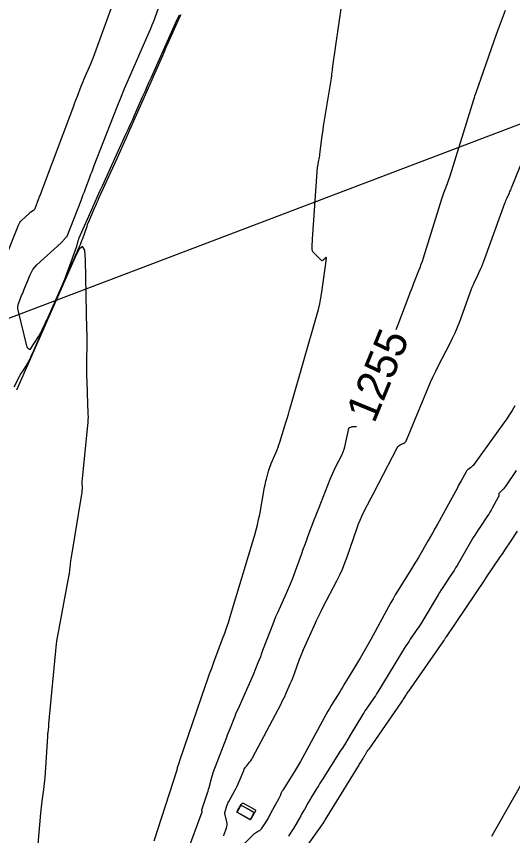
# Model space of a CAD drawing. Extents: x 658976 to 668726, y 639543 to 647196.
# Drawn here: x 661779.9 to 661874.7, y 641576.8 to 641733.2 of the extents above; entities that cross this region are included whole.
import ezdxf

# ---------------------------------------------------------------- set-up
doc = ezdxf.new("R2010")
doc.units = 0
for name, color, linetype in [('Ex_Contour Labels', 7, 'Continuous'), ('Ex_Major Contours', 7, 'Continuous'), ('Ex_Minor Contours', 7, 'Continuous'), ('R_Water', 7, 'Continuous')]:
    doc.layers.add(name, color=color, linetype=linetype)

msp = doc.modelspace()

# ---------------------------------------------------------------- linework, layer by layer
at = {"layer": 'Ex_Major Contours'}
for points in [[(661810.98, 641733.47), (661810.5, 641732.41), (661805.65, 641721.56), (661805.24, 641720.65), (661804.83, 641719.74), (661804.43, 641718.83), (661804.02, 641717.91), (661802.41, 641714.27), (661802, 641713.35), (661801.59, 641712.44), (661801.18, 641711.53), (661800.77, 641710.63), (661796.28, 641700.81), (661795.82, 641699.8), (661795.36, 641698.78), (661794.9, 641697.76), (661794.45, 641696.74), (661791.86, 641690.85), (661791.8, 641690.73), (661791.76, 641690.6), (661791.71, 641690.47), (661791.68, 641690.34), (661791.54, 641689.8), (661791.5, 641689.67), (661791.47, 641689.54), (661791.42, 641689.41), (661791.38, 641689.28), (661789.79, 641684.85), (661789.51, 641684.07), (661789.21, 641683.29), (661788.89, 641682.53), (661788.57, 641681.76), (661785.91, 641675.73), (661785.77, 641675.42), (661785.63, 641675.12), (661785.49, 641674.81), (661785.35, 641674.51), (661784.78, 641673.3), (661784.63, 641673), (661784.47, 641672.71), (661784.3, 641672.42), (661784.13, 641672.14), (661782.48, 641669.62), (661782.47, 641669.61), (661782.46, 641669.6), (661782.44, 641669.6), (661782.43, 641669.6), (661782.36, 641669.62), (661782.34, 641669.62), (661782.33, 641669.63), (661782.32, 641669.64), (661782.3, 641669.65), (661782.1, 641669.86), (661782.07, 641669.9), (661782.04, 641669.94), (661782.01, 641669.99), (661782, 641670.04), (661780.25, 641677.09), (661780.19, 641677.45), (661780.18, 641677.8), (661780.24, 641678.15), (661780.35, 641678.5), (661780.92, 641679.88), (661781.06, 641680.22), (661781.2, 641680.57), (661781.34, 641680.91), (661781.48, 641681.26), (661782.52, 641683.85), (661782.77, 641684.38), (661783.07, 641684.87), (661783.42, 641685.33), (661783.83, 641685.75), (661788.44, 641689.98), (661788.55, 641690.08), (661788.65, 641690.19), (661788.76, 641690.3), (661788.86, 641690.41), (661789.42, 641691.05), (661789.44, 641691.06), (661789.45, 641691.08), (661789.47, 641691.1), (661789.49, 641691.11), (661789.58, 641691.16), (661789.6, 641691.17), (661789.62, 641691.19), (661789.63, 641691.21), (661789.64, 641691.23), (661792.27, 641698.07), (661792.48, 641698.62), (661792.69, 641699.18), (661792.9, 641699.73), (661793.11, 641700.29), (661793.94, 641702.5), (661794.15, 641703.06), (661794.36, 641703.61), (661794.57, 641704.16), (661794.78, 641704.72), (661798.45, 641714.17), (661799.14, 641715.93), (661799.85, 641717.68), (661800.58, 641719.42), (661801.33, 641721.15), (661805.29, 641730.18), (661805.59, 641730.89), (661805.88, 641731.59), (661806.16, 641732.3), (661806.42, 641733.02), (661807.46, 641735.89)], [(661852.46, 641673.42), (661852.84, 641674.4), (661854.92, 641679.88), (661855.15, 641680.48), (661855.39, 641681.08), (661855.62, 641681.68), (661855.85, 641682.28), (661856.8, 641684.68), (661857.03, 641685.28), (661857.25, 641685.88), (661857.46, 641686.49), (661857.66, 641687.1), (661861.2, 641698.4), (661861.32, 641698.76), (661861.44, 641699.13), (661861.57, 641699.5), (661861.71, 641699.86), (661862.27, 641701.31), (661862.4, 641701.67), (661862.54, 641702.04), (661862.66, 641702.4), (661862.78, 641702.77), (661867.29, 641717.35), (661867.4, 641717.69), (661867.51, 641718.02), (661867.62, 641718.36), (661867.73, 641718.69), (661871.63, 641729.85), (661872.17, 641731.37), (661872.75, 641732.88), (661873.35, 641734.39)], [(661812.53, 641573.5), (661815.38, 641581.29), (661815.39, 641581.32), (661815.39, 641581.35), (661815.39, 641581.38), (661815.39, 641581.41), (661815.36, 641581.53), (661815.35, 641581.56), (661815.35, 641581.59), (661815.35, 641581.62), (661815.36, 641581.65), (661816.32, 641584.55), (661816.43, 641584.9), (661816.53, 641585.25), (661816.63, 641585.61), (661816.73, 641585.97), (661817.09, 641587.4), (661817.19, 641587.75), (661817.29, 641588.11), (661817.41, 641588.46), (661817.53, 641588.8), (661820.1, 641595.56), (661820.27, 641596.01), (661820.45, 641596.46), (661820.62, 641596.91), (661820.8, 641597.36), (661821.5, 641599.14), (661821.68, 641599.59), (661821.86, 641600.03), (661822.05, 641600.47), (661822.25, 641600.91), (661824.21, 641605.24), (661824.47, 641605.81), (661824.72, 641606.38), (661824.96, 641606.95), (661825.19, 641607.52), (661826.12, 641609.83), (661826.35, 641610.41), (661826.58, 641610.99), (661826.8, 641611.57), (661827.02, 641612.15), (661828.49, 641616.06), (661828.81, 641616.9), (661829.15, 641617.74), (661829.5, 641618.57), (661829.87, 641619.39), (661831.53, 641623.03), (661831.92, 641623.92), (661832.29, 641624.81), (661832.65, 641625.71), (661832.98, 641626.61), (661834.43, 641630.65), (661834.72, 641631.45), (661835.01, 641632.25), (661835.31, 641633.05), (661835.6, 641633.85), (661836.8, 641637.04), (661837.11, 641637.84), (661837.41, 641638.63), (661837.72, 641639.43), (661838.04, 641640.22), (661839.87, 641644.8), (661840.11, 641645.38), (661840.36, 641645.96), (661840.63, 641646.54), (661840.9, 641647.11), (661842.12, 641649.55), (661842.34, 641650.04), (661842.53, 641650.53), (661842.68, 641651.03), (661842.8, 641651.55), (661843.4, 641654.49), (661843.43, 641654.57), (661843.47, 641654.64), (661843.54, 641654.69), (661843.62, 641654.73), (661843.97, 641654.85), (661844.05, 641654.87), (661844.14, 641654.89), (661844.23, 641654.91), (661844.33, 641654.91), (661844.87, 641654.92)], [(661875.37, 641646.5), (661873.25, 641643.35), (661873.15, 641643.21), (661873.04, 641643.08), (661872.93, 641642.95), (661872.81, 641642.83), (661872.19, 641642.23), (661872.14, 641642.17), (661872.1, 641642.11), (661872.08, 641642.04), (661872.07, 641641.97), (661872.05, 641641.66), (661872.05, 641641.58), (661872.03, 641641.51), (661872, 641641.44), (661871.97, 641641.37), (661870.8, 641639.27), (661870.59, 641638.9), (661870.37, 641638.53), (661870.14, 641638.17), (661869.9, 641637.82), (661868.42, 641635.63), (661868.1, 641635.14), (661867.79, 641634.65), (661867.48, 641634.16), (661867.18, 641633.66), (661864.09, 641628.35), (661863.81, 641627.88), (661863.51, 641627.4), (661863.21, 641626.93), (661862.91, 641626.47), (661861.66, 641624.62), (661861.35, 641624.15), (661861.05, 641623.68), (661860.75, 641623.21), (661860.46, 641622.74), (661857.15, 641617.21), (661856.92, 641616.84), (661856.68, 641616.46), (661856.43, 641616.09), (661856.18, 641615.73), (661855.16, 641614.27), (661854.91, 641613.91), (661854.67, 641613.54), (661854.43, 641613.17), (661854.19, 641612.79), (661848.97, 641604.23), (661848.73, 641603.85), (661848.5, 641603.48), (661848.25, 641603.11), (661848, 641602.74), (661846.99, 641601.29), (661846.74, 641600.92), (661846.5, 641600.56), (661846.26, 641600.18), (661846.03, 641599.8), (661843.69, 641595.92), (661843.22, 641595.15), (661842.75, 641594.38), (661842.27, 641593.61), (661841.78, 641592.85), (661838.33, 641587.43), (661838.08, 641587.05), (661837.84, 641586.66), (661837.6, 641586.28), (661837.37, 641585.89), (661836.31, 641584.17), (661836.13, 641583.87), (661835.95, 641583.58), (661835.77, 641583.28), (661835.6, 641582.97), (661834.92, 641581.76), (661834.75, 641581.46), (661834.57, 641581.16), (661834.4, 641580.85), (661834.23, 641580.55), (661832.84, 641578.13), (661832.54, 641577.64), (661832.24, 641577.14), (661831.92, 641576.66)]]:
    msp.add_lwpolyline(points, dxfattribs=at)
at = {"layer": 'Ex_Minor Contours'}
for points in [[(661775.27, 641680.85), (661780.3, 641693.33), (661780.42, 641693.61), (661780.58, 641693.86), (661780.76, 641694.1), (661780.98, 641694.32), (661782.26, 641695.5), (661782.3, 641695.53), (661782.33, 641695.56), (661782.36, 641695.6), (661782.39, 641695.63), (661782.52, 641695.78), (661782.55, 641695.81), (661782.59, 641695.84), (661782.62, 641695.87), (661782.66, 641695.89), (661783.2, 641696.2), (661783.3, 641696.27), (661783.38, 641696.34), (661783.45, 641696.44), (661783.5, 641696.54), (661784.23, 641698.45), (661784.36, 641698.8), (661784.5, 641699.15), (661784.63, 641699.51), (661784.77, 641699.87), (661790.86, 641716.13), (661791.03, 641716.6), (661791.21, 641717.07), (661791.39, 641717.54), (661791.57, 641718), (661792.3, 641719.87), (661792.48, 641720.34), (661792.67, 641720.8), (661792.86, 641721.26), (661793.06, 641721.72), (661793.87, 641723.57), (661794.07, 641724.03), (661794.26, 641724.49), (661794.44, 641724.96), (661794.62, 641725.43), (661800.54, 641741.8)], [(661806.25, 641575.74), (661810.61, 641589.31), (661810.62, 641589.34), (661810.63, 641589.38), (661810.64, 641589.41), (661810.64, 641589.45), (661810.66, 641589.6), (661810.67, 641589.64), (661810.68, 641589.67), (661810.68, 641589.71), (661810.7, 641589.74), (661810.99, 641590.64), (661811.04, 641590.8), (661811.09, 641590.96), (661811.15, 641591.12), (661811.2, 641591.28), (661816.05, 641605.4), (661816.44, 641606.52), (661816.83, 641607.64), (661817.24, 641608.76), (661817.65, 641609.87), (661819.31, 641614.31), (661819.71, 641615.43), (661820.1, 641616.55), (661820.47, 641617.67), (661820.82, 641618.8), (661825.44, 641634.17), (661825.72, 641635.15), (661825.97, 641636.13), (661826.19, 641637.12), (661826.39, 641638.11), (661827.33, 641643.33), (661827.41, 641643.72), (661827.49, 641644.1), (661827.58, 641644.48), (661827.68, 641644.85), (661828.09, 641646.36), (661828.2, 641646.73), (661828.32, 641647.1), (661828.45, 641647.47), (661828.6, 641647.83), (661829.51, 641649.97), (661829.71, 641650.44), (661829.89, 641650.93), (661830.06, 641651.41), (661830.22, 641651.9), (661831.39, 641655.65), (661831.63, 641656.44), (661831.87, 641657.23), (661832.11, 641658.03), (661832.34, 641658.82), (661837.32, 641676.15), (661837.61, 641677.24), (661837.86, 641678.34), (661838.08, 641679.45), (661838.25, 641680.56), (661839.12, 641686.99), (661839.13, 641687.1), (661839.1, 641687.15), (661839.04, 641687.14), (661838.95, 641687.07), (661838.53, 641686.66), (661838.42, 641686.58), (661838.31, 641686.56), (661838.21, 641686.58), (661838.1, 641686.66), (661836.65, 641688.12), (661836.56, 641688.23), (661836.49, 641688.35), (661836.45, 641688.49), (661836.44, 641688.63), (661836.44, 641689.31), (661836.44, 641689.42), (661836.44, 641689.54), (661836.44, 641689.65), (661836.44, 641689.77), (661836.45, 641690.23), (661836.46, 641690.35), (661836.46, 641690.47), (661836.47, 641690.58), (661836.48, 641690.7), (661837.34, 641703.52), (661837.37, 641703.8), (661837.4, 641704.09), (661837.44, 641704.37), (661837.49, 641704.65), (661837.7, 641705.76), (661837.76, 641706.04), (661837.8, 641706.32), (661837.85, 641706.61), (661837.88, 641706.89), (661838.26, 641709.9), (661838.34, 641710.49), (661838.42, 641711.08), (661838.51, 641711.68), (661838.6, 641712.27), (661840.08, 641721.41), (661840.11, 641721.61), (661840.14, 641721.8), (661840.16, 641721.99), (661840.19, 641722.18), (661840.27, 641722.95), (661840.3, 641723.14), (661840.32, 641723.34), (661840.35, 641723.53), (661840.37, 641723.72), (661842.07, 641735.57)], [(661811.3, 641733.52), (661811.1, 641733.08), (661810.89, 641732.63), (661809.19, 641728.82), (661808.84, 641728.04), (661808.49, 641727.26), (661808.14, 641726.47), (661807.8, 641725.69), (661799.03, 641705.91), (661798.66, 641705.07), (661798.29, 641704.23), (661797.91, 641703.39), (661797.53, 641702.56), (661795.69, 641698.54), (661795.46, 641698.05), (661795.24, 641697.55), (661795.02, 641697.05), (661794.8, 641696.55), (661793.53, 641693.68), (661793.5, 641693.61), (661793.48, 641693.55), (661793.46, 641693.49), (661793.44, 641693.42), (661793.37, 641693.16), (661793.36, 641693.1), (661793.34, 641693.03), (661793.32, 641692.97), (661793.3, 641692.91), (661792.52, 641690.74), (661792.38, 641690.36), (661792.23, 641689.98), (661792.08, 641689.61), (661791.92, 641689.23), (661782.91, 641668.77), (661782.83, 641668.6), (661782.75, 641668.42), (661782.67, 641668.25), (661782.59, 641668.08), (661782.27, 641667.4), (661782.19, 641667.23), (661782.1, 641667.06), (661782, 641666.9), (661781.9, 641666.74), (661781.06, 641665.46), (661780.89, 641665.19), (661780.73, 641664.92), (661780.57, 641664.64), (661780.42, 641664.36), (661779.42, 641662.42)], [(661819.53, 641576.74), (661819.63, 641577.03), (661820.06, 641578.2), (661820.14, 641578.49), (661820.18, 641578.78), (661820.18, 641579.07), (661820.13, 641579.37), (661819.8, 641580.71), (661819.76, 641580.93), (661819.76, 641581.15), (661819.78, 641581.36), (661819.83, 641581.58), (661820.12, 641582.43), (661820.19, 641582.64), (661820.28, 641582.84), (661820.37, 641583.05), (661820.47, 641583.25), (661821.67, 641585.39), (661821.89, 641585.8), (661822.1, 641586.22), (661822.3, 641586.64), (661822.48, 641587.07), (661823.35, 641589.21), (661823.45, 641589.43), (661823.57, 641589.64), (661823.7, 641589.84), (661823.85, 641590.03), (661824.46, 641590.78), (661824.61, 641590.97), (661824.75, 641591.16), (661824.88, 641591.37), (661824.99, 641591.58), (661830.46, 641601.94), (661830.7, 641602.41), (661830.93, 641602.88), (661831.16, 641603.35), (661831.38, 641603.83), (661832.24, 641605.75), (661832.45, 641606.23), (661832.65, 641606.72), (661832.84, 641607.21), (661833.03, 641607.7), (661834.01, 641610.43), (661834.24, 641611.04), (661834.49, 641611.66), (661834.74, 641612.27), (661835, 641612.87), (661836.85, 641616.97), (661837.25, 641617.85), (661837.67, 641618.72), (661838.1, 641619.59), (661838.54, 641620.45), (661841.15, 641625.43), (661841.71, 641626.54), (661842.22, 641627.67), (661842.68, 641628.82), (661843.11, 641629.99), (661845, 641635.56), (661845.27, 641636.3), (661845.56, 641637.03), (661845.88, 641637.75), (661846.24, 641638.45), (661847.7, 641641.25), (661848.06, 641641.95), (661848.43, 641642.65), (661848.79, 641643.35), (661849.16, 641644.05), (661852.68, 641650.84), (661852.79, 641651), (661852.91, 641651.15), (661853.06, 641651.27), (661853.23, 641651.37), (661853.95, 641651.72), (661854.12, 641651.82), (661854.26, 641651.94), (661854.38, 641652.09), (661854.46, 641652.26), (661858.57, 641662.27), (661859.03, 641663.35), (661859.51, 641664.42), (661860.02, 641665.48), (661860.55, 641666.52), (661862.72, 641670.68), (661863.24, 641671.73), (661863.73, 641672.8), (661864.19, 641673.88), (661864.61, 641674.97), (661866.81, 641680.98), (661867, 641681.49), (661867.2, 641682), (661867.42, 641682.5), (661867.65, 641682.99), (661868.57, 641684.96), (661868.8, 641685.46), (661869.01, 641685.96), (661869.21, 641686.46), (661869.4, 641686.97), (661873.23, 641697.55), (661873.32, 641697.8), (661873.42, 641698.05), (661873.52, 641698.29), (661873.63, 641698.54), (661874.08, 641699.51), (661874.19, 641699.75), (661874.3, 641699.99), (661874.4, 641700.24), (661874.5, 641700.48), (661881.26, 641717.1)], [(661784.06, 641575.15), (661784.57, 641581.06), (661784.62, 641581.63), (661784.68, 641582.19), (661784.75, 641582.76), (661784.83, 641583.32), (661785.15, 641585.57), (661785.23, 641586.13), (661785.3, 641586.69), (661785.35, 641587.26), (661785.39, 641587.82), (661785.9, 641595.67), (661785.92, 641595.86), (661785.93, 641596.06), (661785.95, 641596.26), (661785.97, 641596.46), (661786.09, 641597.56), (661786.09, 641597.6), (661786.1, 641597.65), (661786.1, 641597.69), (661786.1, 641597.74), (661786.11, 641597.92), (661786.12, 641597.96), (661786.12, 641598.01), (661786.12, 641598.05), (661786.13, 641598.1), (661787.58, 641613.37), (661787.58, 641613.46), (661787.59, 641613.54), (661787.62, 641613.79), (661787.62, 641613.8), (661787.62, 641613.81), (661787.62, 641613.82), (661787.63, 641613.87), (661787.63, 641613.88), (661787.63, 641613.9), (661790, 641626.53), (661790.05, 641626.78), (661790.09, 641627.03), (661790.12, 641627.28), (661790.15, 641627.53), (661790.25, 641628.55), (661790.28, 641628.8), (661790.31, 641629.05), (661790.34, 641629.3), (661790.38, 641629.55), (661792.46, 641642.33), (661792.49, 641642.55), (661792.51, 641642.77), (661792.52, 641642.99), (661792.52, 641643.21), (661792.5, 641644.09), (661792.5, 641644.31), (661792.5, 641644.53), (661792.52, 641644.75), (661792.54, 641644.97), (661793.58, 641655.08), (661793.63, 641655.63), (661793.65, 641656.17), (661793.66, 641656.72), (661793.65, 641657.26), (661793.55, 641659.45), (661793.53, 641659.99), (661793.51, 641660.54), (661793.49, 641661.09), (661793.48, 641661.63), (661793.39, 641664.76), (661793.38, 641665.47), (661793.37, 641666.17), (661793.36, 641666.87), (661793.37, 641667.58), (661793.41, 641670.5), (661793.41, 641671.22), (661793.41, 641671.94), (661793.41, 641672.66), (661793.39, 641673.38), (661793.13, 641686.7), (661792.97, 641688.57), (661792.56, 641689.26), (661791.93, 641688.78), (661791.05, 641687.12), (661779.91, 641661.81)], [(661875.11, 641658.81), (661874.63, 641657.97), (661874.13, 641657.15), (661873.6, 641656.35), (661873.05, 641655.56), (661867.14, 641647.47), (661867.04, 641647.35), (661866.94, 641647.24), (661866.83, 641647.14), (661866.7, 641647.04), (661866.2, 641646.69), (661866.08, 641646.59), (661865.97, 641646.49), (661865.88, 641646.37), (661865.8, 641646.24), (661864.87, 641644.52), (661864.69, 641644.19), (661864.51, 641643.86), (661864.33, 641643.53), (661864.15, 641643.19), (661860.35, 641636.24), (661859.92, 641635.45), (661859.48, 641634.67), (661859.03, 641633.89), (661858.58, 641633.11), (661856.7, 641629.89), (661856.27, 641629.17), (661855.84, 641628.45), (661855.4, 641627.73), (661854.96, 641627.02), (661853.17, 641624.17), (661852.72, 641623.45), (661852.29, 641622.73), (661851.87, 641622), (661851.47, 641621.26), (661847.64, 641614.23), (661847.14, 641613.33), (661846.63, 641612.42), (661846.1, 641611.52), (661845.57, 641610.63), (661842.99, 641606.37), (661842.67, 641605.84), (661842.34, 641605.31), (661842.01, 641604.77), (661841.68, 641604.24), (661840.36, 641602.13), (661840.04, 641601.6), (661839.72, 641601.06), (661839.41, 641600.52), (661839.11, 641599.97), (661834.55, 641591.59), (661834.19, 641590.93), (661833.81, 641590.28), (661833.43, 641589.64), (661833.04, 641589), (661830.8, 641585.45), (661830.72, 641585.32), (661830.65, 641585.19), (661830.58, 641585.05), (661830.52, 641584.92), (661830.28, 641584.36), (661830.22, 641584.22), (661830.16, 641584.08), (661830.09, 641583.95), (661830.02, 641583.82), (661829.65, 641583.15), (661829.56, 641582.99), (661829.48, 641582.83), (661829.39, 641582.68), (661829.31, 641582.52), (661828.4, 641580.86), (661828.23, 641580.54), (661828.05, 641580.23), (661827.86, 641579.91), (661827.67, 641579.6), (661826.7, 641578.06), (661826.6, 641577.92), (661826.48, 641577.79), (661826.34, 641577.68), (661826.19, 641577.58), (661825.56, 641577.21), (661825.41, 641577.12), (661825.27, 641577.01), (661825.13, 641576.9), (661824.99, 641576.78), (661823.33, 641575.12)], [(661875.6, 641634.89), (661873.96, 641632.48), (661873.55, 641631.87), (661873.14, 641631.27), (661872.74, 641630.66), (661872.33, 641630.06), (661869.53, 641625.93), (661869.52, 641625.91), (661869.51, 641625.89), (661869.49, 641625.87), (661869.48, 641625.85), (661869.43, 641625.76), (661869.42, 641625.74), (661869.41, 641625.72), (661869.39, 641625.7), (661869.38, 641625.68), (661861.98, 641614.7), (661861.94, 641614.64), (661861.9, 641614.58), (661861.87, 641614.52), (661861.83, 641614.46), (661861.68, 641614.21), (661861.64, 641614.15), (661861.6, 641614.09), (661861.57, 641614.03), (661861.52, 641613.97), (661854.8, 641604.37), (661854.68, 641604.2), (661854.57, 641604.03), (661854.46, 641603.86), (661854.35, 641603.69), (661853.93, 641602.99), (661853.82, 641602.82), (661853.71, 641602.65), (661853.6, 641602.48), (661853.49, 641602.31), (661847.21, 641593.28), (661847.11, 641593.13), (661847.01, 641592.98), (661846.92, 641592.83), (661846.82, 641592.68), (661846.45, 641592.07), (661846.36, 641591.91), (661846.27, 641591.76), (661846.17, 641591.61), (661846.08, 641591.46), (661845.54, 641590.62), (661845.42, 641590.42), (661845.3, 641590.23), (661845.18, 641590.04), (661845.06, 641589.85), (661838.9, 641579.82), (661838.88, 641579.79), (661838.86, 641579.75), (661838.83, 641579.71), (661838.81, 641579.67), (661838.72, 641579.51), (661838.7, 641579.47), (661838.68, 641579.43), (661838.65, 641579.39), (661838.63, 641579.36), (661838.45, 641579.04), (661838.41, 641578.98), (661838.37, 641578.91), (661838.33, 641578.85), (661838.29, 641578.79), (661829.31, 641566.23)], [(661870.75, 641576.67), (661871.04, 641577.2), (661880.69, 641594.08)]]:
    msp.add_lwpolyline(points, dxfattribs=at)
for points in [[(661824.96, 641582.01), (661825.03, 641581.97), (661825.11, 641581.93), (661825.19, 641581.88), (661825.49, 641581.71), (661825.55, 641581.67), (661825.59, 641581.61), (661825.59, 641581.55), (661825.56, 641581.47), (661824.76, 641580.02), (661824.69, 641579.91), (661824.63, 641579.79), (661824.61, 641579.77), (661824.59, 641579.76), (661824.57, 641579.76), (661824.54, 641579.77), (661822.81, 641580.77), (661822.73, 641580.81), (661822.65, 641580.86), (661822.57, 641580.91), (661822.48, 641580.95), (661822.05, 641581.2), (661822.03, 641581.21), (661822.02, 641581.23), (661822.02, 641581.26), (661822.03, 641581.28), (661822.1, 641581.39), (661822.12, 641581.41), (661822.14, 641581.44), (661822.16, 641581.47), (661822.17, 641581.5), (661822.85, 641582.67), (661822.98, 641582.84), (661823.13, 641582.92), (661823.3, 641582.92), (661823.49, 641582.85), (661824.88, 641582.06)], [(661823.68, 641582.1), (661823.8, 641582.03), (661823.92, 641581.96), (661824.03, 641581.9), (661825.14, 641581.28), (661825.22, 641581.22), (661825.26, 641581.15), (661825.26, 641581.06), (661825.23, 641580.97), (661824.97, 641580.51), (661824.89, 641580.37), (661824.82, 641580.23), (661824.66, 641579.94), (661824.62, 641579.88), (661824.56, 641579.86), (661824.51, 641579.85), (661824.44, 641579.88), (661823.89, 641580.2), (661823.77, 641580.26), (661823.66, 641580.33), (661823.54, 641580.39), (661823.43, 641580.46), (661822.17, 641581.17), (661822.12, 641581.21), (661822.09, 641581.26), (661822.09, 641581.32), (661822.12, 641581.38), (661822.31, 641581.64), (661822.36, 641581.71), (661822.4, 641581.77), (661822.44, 641581.84), (661822.48, 641581.91), (661822.74, 641582.37), (661822.81, 641582.45), (661822.88, 641582.49), (661822.96, 641582.49), (661823.06, 641582.45), (661823.56, 641582.16)]]:
    msp.add_lwpolyline(points, close=True, dxfattribs=at)
at = {"layer": 'R_Water'}
msp.add_line((661564.22, 641594.16), (662140.69, 641813.25), dxfattribs=at)

# ---------------------------------------------------------------- texts
at = {"layer": 'Ex_Contour Labels'}
msp.add_text('1255', height=6, rotation=67.6992, dxfattribs=at).set_placement((661848.28, 641655.32))

doc.saveas('drawing.dxf')
